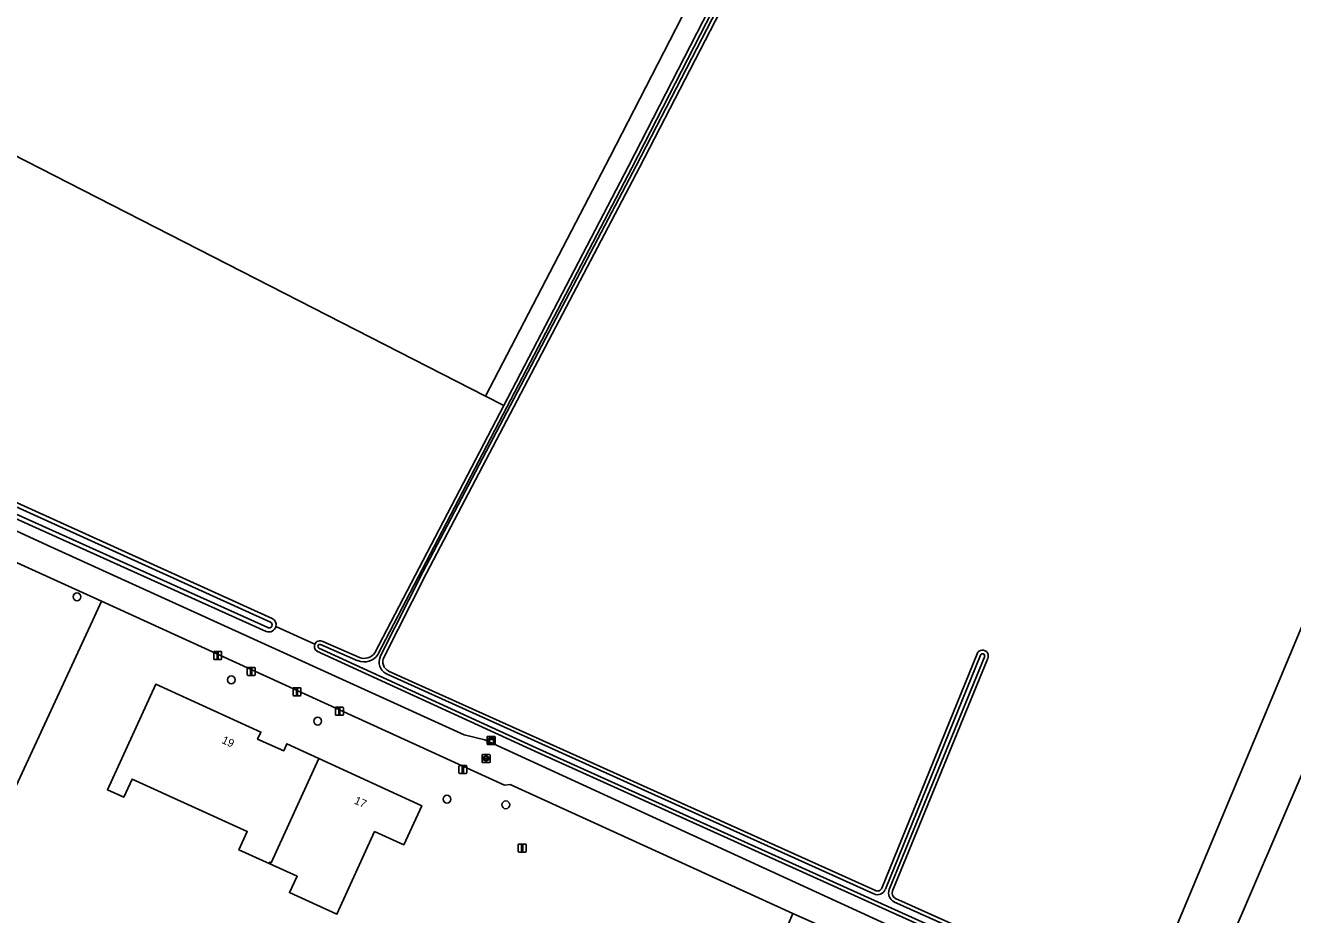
# Model space of a CAD drawing. Extents: x 155209 to 156748, y 385356 to 388487.
# Drawn here: x 155777.4 to 155935.8, y 386006.7 to 386117.9 of the extents above; entities that cross this region are included whole.
import ezdxf

# ---------------------------------------------------------------- set-up
doc = ezdxf.new("R2010")
doc.units = 0
for name, color, linetype in [('IMGEO_Berm_groen', 7, 'Continuous'), ('IMGEO_Boom', 7, 'Continuous'), ('IMGEO_Bouwland', 7, 'Continuous'), ('IMGEO_Erf', 7, 'Continuous'), ('IMGEO_Grasland_overig', 7, 'Continuous'), ('IMGEO_Groenvoorziening', 7, 'Continuous'), ('IMGEO_Kast', 7, 'Continuous'), ('IMGEO_Lichtmast', 7, 'Continuous'), ('IMGEO_Loofbos', 7, 'Continuous'), ('IMGEO_Oever', 7, 'Continuous'), ('IMGEO_Pand', 7, 'Continuous'), ('IMGEO_Pand_nummerreeks', 7, 'Continuous'), ('IMGEO_Rijbaan_lokaal_gesloten', 7, 'Continuous'), ('IMGEO_Rijbaan_lokaal_open', 7, 'Continuous'), ('IMGEO_Rioolput', 7, 'Continuous'), ('IMGEO_Waterloop', 7, 'Continuous')]:
    doc.layers.add(name, color=color, linetype=linetype)

msp = doc.modelspace()

# ---------------------------------------------------------------- linework, layer by layer
at = {"layer": 'IMGEO_Berm_groen'}
for points in [[(156017.72, 386241.8), (155997.34, 386192.47), (155999.28, 386187.65), (155999.02, 386187.05), (155959.3, 386096.17), (155916.98, 385994.93), (155916.27, 385993.23), (155920.08, 385991.51), (155920.81, 385993.21), (155925.38, 386003.82), (155927.74, 386002.82), (155959.53, 386076.88), (155989.7, 386147.22), (156003.54, 386179.53)], [(155888.76, 386000), (155873.35, 386006.89), (155872.65, 386005.2)]]:
    msp.add_lwpolyline(points, dxfattribs=at)
at = {"layer": 'IMGEO_Boom'}
for centre in [(155783.88, 386046.46), (155803.17, 386036.08), (155813.96, 386030.92), (155830.12, 386021.16), (155837.48, 386020.46)]:
    msp.add_circle(centre, 0.489, dxfattribs=at)
at = {"layer": 'IMGEO_Bouwland'}
msp.add_lwpolyline([(155823.3, 386267.6), (155780.71, 386286.96), (155779.89, 386287.34), (155779.73, 386287.01), (155776.23, 386279.85), (155777.11, 386279.38), (155729.56, 386186.22), (155707.56, 386142.3), (155686.33, 386100.64), (155728.14, 386080.19), (155746.94, 386116.53), (155834.92, 386071.53), (155850.53, 386101.48), (155869.89, 386139.18), (155897.23, 386193.45), (155910.33, 386221.05), (155911.39, 386223.4)], dxfattribs=at)
at = {"layer": 'IMGEO_Erf'}
for points in [[(155853.12, 385955.51), (155846.2, 385958.41), (155852.48, 385973.4), (155859.4, 385970.5), (155868.12, 385991.46), (155867.03, 385991.83), (155872.65, 386005.2), (155873.35, 386006.89), (155838.02, 386023), (155837.33, 386022.91), (155786.93, 386045.9), (155786.05, 386043.98), (155767.96, 386004.93), (155765.9, 386000.59), (155785.57, 385991.44), (155812.34, 385978.74), (155809.88, 385972.63), (155808.05, 385968.03), (155801.87, 385953.41), (155776.85, 385893.52), (155754.19, 385839.25), (155761.09, 385835.71), (155796.45, 385820.47), (155833.54, 385909.24)], [(155810.44, 386009.49), (155811.38, 386011.53), (155807.89, 386013.12), (155804.11, 386014.84), (155805.15, 386017.11), (155790.77, 386023.67), (155789.73, 386021.41), (155787.68, 386022.34), (155793.73, 386035.53), (155806.86, 386029.55), (155806.45, 386028.65), (155809.73, 386027.2), (155810.11, 386028.08), (155814.1, 386026.24), (155826.96, 386020.35), (155824.75, 386015.47), (155821.08, 386017.11), (155816.36, 386006.79)]]:
    msp.add_lwpolyline(points, close=True, dxfattribs=at)
at = {"layer": 'IMGEO_Grasland_overig'}
for points in [[(155913.39, 386222.52), (155911.39, 386223.4), (155910.33, 386221.05), (155897.23, 386193.45), (155869.89, 386139.18), (155850.53, 386101.48), (155834.92, 386071.53), (155837.21, 386070.36)], [(155837.21, 386070.36), (155852.82, 386100.29), (155872.18, 386138.01), (155899.55, 386192.32), (155913.61, 386221.94)]]:
    msp.add_lwpolyline(points, dxfattribs=at)
msp.add_lwpolyline([(155767.96, 386004.93), (155786.05, 386043.98), (155786.93, 386045.9), (155774.57, 386051.53), (155773.63, 386049.48), (155755.36, 386009.95), (155753.63, 386006.21), (155765.9, 386000.59)], close=True, dxfattribs=at)
at = {"layer": 'IMGEO_Groenvoorziening'}
for points in [[(155549.69, 386159.71), (155563.67, 386153.1), (155579.39, 386146.58), (155591.1, 386142.16), (155584.82, 386143.24), (155577.96, 386145.45), (155590.64, 386139.37), (155598.08, 386135.8), (155658.12, 386108.28), (155736.9, 386072.88), (155759.83, 386062.69), (155766.03, 386059.41), (155780.61, 386052.71), (155832.25, 386029.22), (155834.86, 386028.6), (155915.05, 385991.74), (155919.39, 385989.89), (155919.66, 385990.52), (155920.08, 385991.51), (155916.27, 385993.23), (155901.28, 386000), (155841.09, 386027.17), (155813.87, 386039.65)], [(155807.53, 386042.14), (155738.44, 386073.25)], [(155813.61, 386040.55), (155808.75, 386042.76)]]:
    msp.add_lwpolyline(points, dxfattribs=at)
for centre, radius, start, end in [((155807.87, 386042.96), 0.894, 247.102, 347.1497), ((155814.26, 386040.25), 0.711, 154.8939, 237.4164)]:
    msp.add_arc(centre, radius, start, end, dxfattribs=at)
at = {"layer": 'IMGEO_Kast'}
for p, q in [((155835.14, 386028.09), (155835.14, 386028.93)), ((155835.14, 386028.93), (155835.14, 386028.09)), ((155835.21, 386029.01), (155836.06, 386029.01)), ((155836.06, 386029.01), (155835.21, 386029.01)), ((155836.14, 386028.94), (155836.14, 386028.1)), ((155836.14, 386028.1), (155836.14, 386028.94)), ((155836.07, 386028.01), (155835.22, 386028.01)), ((155835.22, 386028.01), (155836.07, 386028.01))]:
    msp.add_line(p, q, dxfattribs=at)
for points in [[(155835.34, 386028.8), (155835.94, 386028.8), (155835.94, 386028.72), (155835.34, 386028.72), (155835.34, 386028.8)], [(155835.34, 386028.63), (155835.94, 386028.63), (155835.94, 386028.14), (155835.34, 386028.14), (155835.34, 386028.63)]]:
    msp.add_lwpolyline(points, dxfattribs=at)
msp.add_circle((155835.42, 386028.48), 0.0377, dxfattribs=at)
for centre, start, end in [((155835.22, 386028.94), 92.4484, 184.2845), ((155835.22, 386028.94), 92.4484, 184.2845), ((155836.06, 386028.94), 2.4484, 94.2845), ((155836.06, 386028.94), 2.4484, 94.2845), ((155835.22, 386028.09), 182.4484, 274.2845), ((155835.22, 386028.09), 182.4484, 274.2845), ((155836.06, 386028.09), 272.4484, 4.2845), ((155836.06, 386028.09), 272.4484, 4.2845)]:
    msp.add_arc(centre, 0.0779, start, end, dxfattribs=at)
at = {"layer": 'IMGEO_Lichtmast'}
for p, q in [((155800.97, 386038.73), (155800.97, 386039.53)), ((155800.97, 386039.53), (155800.97, 386038.73)), ((155801.07, 386039.63), (155801.86, 386039.63)), ((155801.86, 386039.63), (155801.07, 386039.63)), ((155801.86, 386038.63), (155801.07, 386038.63)), ((155801.07, 386038.63), (155801.86, 386038.63)), ((155801.96, 386039.53), (155801.96, 386038.73)), ((155801.96, 386038.73), (155801.96, 386039.53)), ((155805.15, 386036.74), (155805.15, 386037.54)), ((155805.15, 386037.54), (155805.15, 386036.74)), ((155805.25, 386037.64), (155806.04, 386037.64)), ((155806.04, 386037.64), (155805.25, 386037.64)), ((155806.14, 386037.54), (155806.14, 386036.74)), ((155806.14, 386036.74), (155806.14, 386037.54)), ((155806.04, 386036.64), (155805.25, 386036.64)), ((155805.25, 386036.64), (155806.04, 386036.64)), ((155810.98, 386035.09), (155811.77, 386035.09)), ((155811.77, 386035.09), (155810.98, 386035.09)), ((155810.88, 386034.19), (155810.88, 386034.99)), ((155810.88, 386034.99), (155810.88, 386034.19)), ((155811.77, 386034.09), (155810.98, 386034.09)), ((155810.98, 386034.09), (155811.77, 386034.09)), ((155811.87, 386034.99), (155811.87, 386034.19)), ((155811.87, 386034.19), (155811.87, 386034.99)), ((155816.18, 386031.75), (155816.18, 386032.55)), ((155816.18, 386032.55), (155816.18, 386031.75)), ((155816.28, 386032.65), (155817.07, 386032.65)), ((155817.07, 386032.65), (155816.28, 386032.65)), ((155817.17, 386032.55), (155817.17, 386031.75)), ((155817.17, 386031.75), (155817.17, 386032.55)), ((155817.07, 386031.65), (155816.28, 386031.65)), ((155816.28, 386031.65), (155817.07, 386031.65)), ((155831.62, 386024.47), (155831.62, 386025.27)), ((155831.62, 386025.27), (155831.62, 386024.47)), ((155831.72, 386025.37), (155832.51, 386025.37)), ((155832.51, 386025.37), (155831.72, 386025.37)), ((155832.51, 386024.37), (155831.72, 386024.37)), ((155831.72, 386024.37), (155832.51, 386024.37)), ((155832.61, 386025.27), (155832.61, 386024.47)), ((155832.61, 386024.47), (155832.61, 386025.27)), ((155839.02, 386014.66), (155839.02, 386015.46)), ((155839.02, 386015.46), (155839.02, 386014.66)), ((155839.12, 386015.56), (155839.91, 386015.56)), ((155839.91, 386015.56), (155839.12, 386015.56)), ((155839.91, 386014.56), (155839.12, 386014.56)), ((155839.12, 386014.56), (155839.91, 386014.56)), ((155840.01, 386015.46), (155840.01, 386014.66)), ((155840.01, 386014.66), (155840.01, 386015.46))]:
    msp.add_line(p, q, dxfattribs=at)
for points in [[(155801.39, 386039.51), (155801.54, 386039.51), (155801.54, 386038.76), (155801.39, 386038.76), (155801.39, 386039.51)], [(155805.57, 386037.52), (155805.72, 386037.52), (155805.72, 386036.77), (155805.57, 386036.77), (155805.57, 386037.52)], [(155811.3, 386034.96), (155811.45, 386034.96), (155811.45, 386034.21), (155811.3, 386034.21), (155811.3, 386034.96)], [(155816.6, 386032.53), (155816.75, 386032.53), (155816.75, 386031.78), (155816.6, 386031.78), (155816.6, 386032.53)], [(155832.04, 386025.24), (155832.19, 386025.24), (155832.19, 386024.49), (155832.04, 386024.49), (155832.04, 386025.24)], [(155839.44, 386015.44), (155839.59, 386015.44), (155839.59, 386014.69), (155839.44, 386014.69), (155839.44, 386015.44)]]:
    msp.add_lwpolyline(points, dxfattribs=at)
for centre, start, end in [((155801.07, 386039.53), 90, 180), ((155801.07, 386039.53), 90, 180), ((155801.07, 386038.73), 180, 270), ((155801.07, 386038.73), 180, 270), ((155801.86, 386039.53), 0, 90), ((155801.86, 386039.53), 360, 90), ((155801.86, 386038.73), 270, 0), ((155801.86, 386038.73), 270, 0), ((155805.25, 386037.54), 90, 180), ((155805.25, 386037.54), 90, 180), ((155805.25, 386036.74), 180, 270), ((155805.25, 386036.74), 180, 270), ((155806.04, 386037.54), 0, 90), ((155806.04, 386037.54), 360, 90), ((155806.04, 386036.74), 270, 0), ((155806.04, 386036.74), 270, 0), ((155810.98, 386034.99), 90, 180), ((155810.98, 386034.99), 90, 180), ((155811.77, 386034.99), 0, 90), ((155811.77, 386034.99), 360, 90), ((155810.98, 386034.19), 180, 270), ((155810.98, 386034.19), 180, 270), ((155811.77, 386034.19), 270, 0), ((155811.77, 386034.19), 270, 0), ((155816.28, 386032.55), 90, 180), ((155816.28, 386032.55), 90, 180), ((155817.07, 386032.55), 0, 90), ((155817.07, 386032.55), 360, 90), ((155816.28, 386031.75), 180, 270), ((155816.28, 386031.75), 180, 270), ((155817.07, 386031.75), 270, 0), ((155817.07, 386031.75), 270, 0), ((155831.72, 386025.27), 90, 180), ((155831.72, 386025.27), 90, 180), ((155831.72, 386024.47), 180, 270), ((155831.72, 386024.47), 180, 270), ((155832.51, 386025.27), 0, 90), ((155832.51, 386025.27), 360, 90), ((155832.51, 386024.47), 270, 0), ((155832.51, 386024.47), 270, 0), ((155839.12, 386015.46), 90, 180), ((155839.12, 386015.46), 90, 180), ((155839.12, 386014.66), 180, 270), ((155839.12, 386014.66), 180, 270), ((155839.91, 386015.46), 0, 90), ((155839.91, 386015.46), 360, 90), ((155839.91, 386014.66), 270, 0), ((155839.91, 386014.66), 270, 0)]:
    msp.add_arc(centre, 0.1, start, end, dxfattribs=at)
at = {"layer": 'IMGEO_Loofbos'}
for points in [[(155825.81, 386265.2), (155838.57, 386259.27), (155857.11, 386250), (155875.07, 386241.03), (155912.74, 386224.24), (155914.38, 386224.1), (155996.15, 386188.3), (155995.42, 386186.63), (155915.31, 386221.64), (155914.94, 386221.5), (155899.02, 386188.41), (155871.23, 386133.09), (155854.18, 386100.13), (155827.56, 386049.39), (155822.24, 386038.89)], [(155886.19, 386008.74), (155905.67, 386000), (155916.98, 385994.93), (155959.3, 386096.17), (155999.02, 386187.05)], [(155821.1, 386039.46), (155837.21, 386070.36), (155834.92, 386071.53), (155746.94, 386116.53), (155728.14, 386080.19), (155727.58, 386079.11), (155738.07, 386074.28)], [(155739.12, 386074.85), (155770.1, 386061.03), (155808.28, 386043.75)], [(155808.75, 386042.76), (155813.61, 386040.55)], [(155814.61, 386040.87), (155819.17, 386038.89)], [(155884.48, 386010.06), (155896.37, 386039.34)], [(155897.68, 386038.68), (155885.82, 386009.71)], [(155822.83, 386037.18), (155883.66, 386009.73)]]:
    msp.add_lwpolyline(points, dxfattribs=at)
for centre, radius, start, end in [((155807.87, 386042.96), 0.896, 347.2846, 62.7618), ((155814.26, 386040.25), 0.71, 60.5107, 155.0748), ((155819.79, 386040.34), 1.58, 246.7052, 325.981), ((155823.35, 386038.32), 1.25, 153.0576, 245.6959), ((155897.05, 386039.07), 0.731, 328.3924, 158.0204), ((155883.91, 386010.3), 0.619, 245.9351, 337.4758), ((155886.53, 386009.42), 0.764, 157.5749, 243.2401)]:
    msp.add_arc(centre, radius, start, end, dxfattribs=at)
at = {"layer": 'IMGEO_Oever'}
for points in [[(155825.61, 386264.79), (155838.37, 386258.86), (155856.91, 386249.6), (155874.87, 386240.62), (155912.62, 386223.8), (155914.26, 386223.65), (155995.54, 386188.08), (155995.17, 386187.24), (155915.32, 386222.13), (155914.61, 386221.86), (155898.62, 386188.61), (155870.82, 386133.3), (155853.78, 386100.34), (155827.16, 386049.6), (155821.83, 386039.09)], [(155822.24, 386038.89), (155827.56, 386049.39), (155854.18, 386100.13), (155871.23, 386133.09), (155899.02, 386188.41), (155914.94, 386221.5), (155915.31, 386221.64), (155995.42, 386186.63), (155996.15, 386188.3), (155914.38, 386224.1), (155912.74, 386224.24), (155875.07, 386241.03), (155857.11, 386250), (155838.57, 386259.27), (155825.81, 386265.2)], [(155913.61, 386221.94), (155899.55, 386192.32), (155872.18, 386138.01), (155852.82, 386100.29), (155837.21, 386070.36), (155821.1, 386039.46)], [(155821.49, 386039.23), (155837.62, 386070.15), (155853.22, 386100.09), (155872.59, 386137.8), (155899.96, 386192.12), (155914.02, 386221.75)], [(155738.44, 386073.25), (155807.53, 386042.14)], [(155807.73, 386042.6), (155738.68, 386073.7)], [(155738.96, 386074.38), (155769.89, 386060.57), (155808.06, 386043.3)], [(155808.28, 386043.75), (155770.1, 386061.03)], [(155885.99, 386008.33), (155905.49, 385999.59), (155915.28, 385995.19), (155914.9, 385994.35), (155901.47, 386000.41), (155841.28, 386027.59), (155814.1, 386040.05)], [(155814.32, 386040.5), (155818.99, 386038.47)], [(155819.17, 386038.89), (155814.61, 386040.87)], [(155813.87, 386039.65), (155841.09, 386027.17), (155901.28, 386000), (155916.27, 385993.23)], [(155896.37, 386039.34), (155884.48, 386010.06)], [(155884.91, 386009.9), (155896.79, 386039.17)], [(155897.33, 386039.03), (155885.4, 386009.88)], [(155885.82, 386009.71), (155897.68, 386038.68)], [(155822.65, 386036.77), (155883.47, 386009.32)], [(155883.66, 386009.73), (155822.83, 386037.18)], [(155916.27, 385993.23), (155916.98, 385994.93), (155905.67, 386000), (155886.19, 386008.74)]]:
    msp.add_lwpolyline(points, dxfattribs=at)
for centre, radius, start, end in [((155807.87, 386042.96), 0.393, 247.6127, 61.5422), ((155807.87, 386042.96), 0.896, 347.2846, 62.7618), ((155807.87, 386042.96), 0.894, 247.102, 347.1497), ((155814.26, 386040.25), 0.711, 154.8939, 237.4164), ((155814.26, 386040.25), 0.71, 60.5107, 155.0748), ((155814.26, 386040.25), 0.26, 76.6054, 231.9822), ((155819.79, 386040.34), 2.03, 246.6263, 326.768), ((155819.79, 386040.34), 1.58, 246.7052, 325.981), ((155823.35, 386038.32), 1.7, 153.1574, 245.715), ((155823.35, 386038.32), 1.25, 153.0576, 245.6959), ((155897.05, 386039.07), 0.731, 328.3924, 158.0204), ((155897.05, 386039.07), 0.278, 352.6896, 158.1298), ((155883.91, 386010.29), 1.07, 245.855, 338.2845), ((155883.91, 386010.3), 0.619, 245.9351, 337.4758), ((155886.53, 386009.42), 1.21, 157.8404, 243.8223), ((155886.53, 386009.42), 0.764, 157.5749, 243.2401)]:
    msp.add_arc(centre, radius, start, end, dxfattribs=at)
at = {"layer": 'IMGEO_Pand'}
for points in [[(155814.1, 386026.24), (155810.11, 386028.08), (155809.73, 386027.2), (155806.45, 386028.65), (155806.86, 386029.55), (155793.73, 386035.53), (155787.68, 386022.34), (155789.73, 386021.41), (155790.77, 386023.67), (155805.15, 386017.11), (155804.11, 386014.84), (155807.89, 386013.12), (155807.97, 386013.29), (155808.14, 386013.21)], [(155814.1, 386026.24), (155808.14, 386013.21), (155807.97, 386013.29), (155807.89, 386013.12), (155811.38, 386011.53), (155810.44, 386009.49), (155816.36, 386006.79), (155821.08, 386017.11), (155824.75, 386015.47), (155826.96, 386020.35)]]:
    msp.add_lwpolyline(points, close=True, dxfattribs=at)
at = {"layer": 'IMGEO_Rijbaan_lokaal_gesloten'}
msp.add_lwpolyline([(155944.24, 386024.53), (155949.14, 386035.92), (155965.64, 386074.34), (155984.91, 386119.23), (156009.58, 386176.82), (156003.54, 386179.53), (155989.7, 386147.22), (155959.53, 386076.88), (155927.74, 386002.82), (155923, 385991.79), (155918.96, 385982.46), (155913.39, 385969.48), (155908.98, 385959.23), (155875.91, 385882.64)], dxfattribs=at)
at = {"layer": 'IMGEO_Rijbaan_lokaal_open'}
msp.add_lwpolyline([(155780.61, 386052.71), (155766.03, 386059.41), (155759.83, 386062.69), (155736.9, 386072.88), (155735.52, 386070.28), (155735.2, 386069.65), (155735.55, 386069.49), (155763.02, 386056.8), (155774.57, 386051.53), (155786.93, 386045.9), (155837.33, 386022.91), (155838.02, 386023), (155873.35, 386006.89), (155888.76, 386000), (155913.8, 385988.81), (155915.05, 385991.74), (155834.86, 386028.6), (155832.25, 386029.22)], close=True, dxfattribs=at)
at = {"layer": 'IMGEO_Rioolput'}
for p, q in [((155834.5, 386025.82), (155834.5, 386026.68)), ((155834.58, 386026.75), (155835.43, 386026.75)), ((155835.43, 386025.75), (155834.58, 386025.75)), ((155834.76, 386026.24), (155834.76, 386026.26)), ((155835.2, 386026.21), (155834.8, 386026.21)), ((155834.81, 386026.29), (155835.2, 386026.29)), ((155834.99, 386026.53), (155835.02, 386026.53)), ((155835.01, 386025.97), (155834.99, 386025.97)), ((155835.25, 386026.26), (155835.25, 386026.24)), ((155835.5, 386026.68), (155835.5, 386025.82))]:
    msp.add_line(p, q, dxfattribs=at)
for points in [[(155834.5, 386025.82), (155834.5, 386026.68)], [(155834.58, 386026.75), (155835.43, 386026.75)], [(155835.43, 386025.75), (155834.58, 386025.75)], [(155835.5, 386026.68), (155835.5, 386025.82)]]:
    msp.add_lwpolyline(points, dxfattribs=at)
for centre, radius, start, end in [((155834.58, 386026.67), 0.0765, 91.552, 178.448), ((155834.58, 386026.67), 0.0765, 91.552, 178.448), ((155834.58, 386025.82), 0.0765, 181.552, 268.448), ((155834.58, 386025.82), 0.0765, 181.552, 268.448), ((155834.8, 386026.25), 0.0403, 85.8775, 175.7526), ((155834.8, 386026.24), 0.0366, 178.938, 274.7102), ((155835.21, 386026.25), 0.0386, 1.7309, 96.639), ((155835.2, 386026.25), 0.043, 264.8664, 352.4533), ((155835.43, 386026.67), 0.0765, 1.552, 88.448), ((155835.43, 386026.67), 0.0765, 1.552, 88.448), ((155835.43, 386025.82), 0.0765, 271.552, 358.448), ((155835.43, 386025.82), 0.0765, 271.552, 358.448)]:
    msp.add_arc(centre, radius, start, end, dxfattribs=at)
for centre, major_axis, ratio, start_param, end_param in [((155834.99, 386026.25), (-0.387, 0.002), 0.722429, 4.712389, 7.853982), ((155835.01, 386026.25), (-0.39, 0.002), 0.717154, 1.570796, 4.712389)]:
    msp.add_ellipse(centre, major_axis=major_axis, ratio=ratio, start_param=start_param, end_param=end_param, dxfattribs=at)
at = {"layer": 'IMGEO_Waterloop'}
for points in [[(155821.83, 386039.09), (155827.16, 386049.6), (155853.78, 386100.34), (155870.82, 386133.3), (155898.62, 386188.61), (155914.61, 386221.86), (155915.32, 386222.13), (155995.17, 386187.24)], [(155914.02, 386221.75), (155899.96, 386192.12), (155872.59, 386137.8), (155853.22, 386100.09), (155837.62, 386070.15), (155821.49, 386039.23)], [(155738.68, 386073.7), (155807.73, 386042.6)], [(155808.06, 386043.3), (155769.89, 386060.57), (155738.96, 386074.38)], [(155814.1, 386040.05), (155841.28, 386027.59), (155901.47, 386000.41), (155914.9, 385994.35), (155915.28, 385995.19), (155905.49, 385999.59), (155885.99, 386008.33)], [(155818.99, 386038.47), (155814.32, 386040.5)], [(155896.79, 386039.17), (155884.91, 386009.9)], [(155885.4, 386009.88), (155897.33, 386039.03)], [(155883.47, 386009.32), (155822.65, 386036.77)]]:
    msp.add_lwpolyline(points, dxfattribs=at)
for centre, radius, start, end in [((155807.87, 386042.96), 0.393, 247.6127, 61.5422), ((155814.26, 386040.25), 0.26, 76.6054, 231.9822), ((155819.79, 386040.34), 2.03, 246.6263, 326.768), ((155823.35, 386038.32), 1.7, 153.1574, 245.715), ((155897.05, 386039.07), 0.278, 352.6896, 158.1298), ((155883.91, 386010.29), 1.07, 245.855, 338.2845), ((155886.53, 386009.42), 1.21, 157.8404, 243.8223)]:
    msp.add_arc(centre, radius, start, end, dxfattribs=at)

# ---------------------------------------------------------------- texts
at = {"layer": 'IMGEO_Pand_nummerreeks'}
for s, rotation, p in [('19', 335.4911, (155801.89, 386028.21)), ('17', 335.3568, (155818.44, 386020.65))]:
    msp.add_text(s, height=1, rotation=rotation, dxfattribs=at).set_placement(p)

doc.saveas('drawing.dxf')
